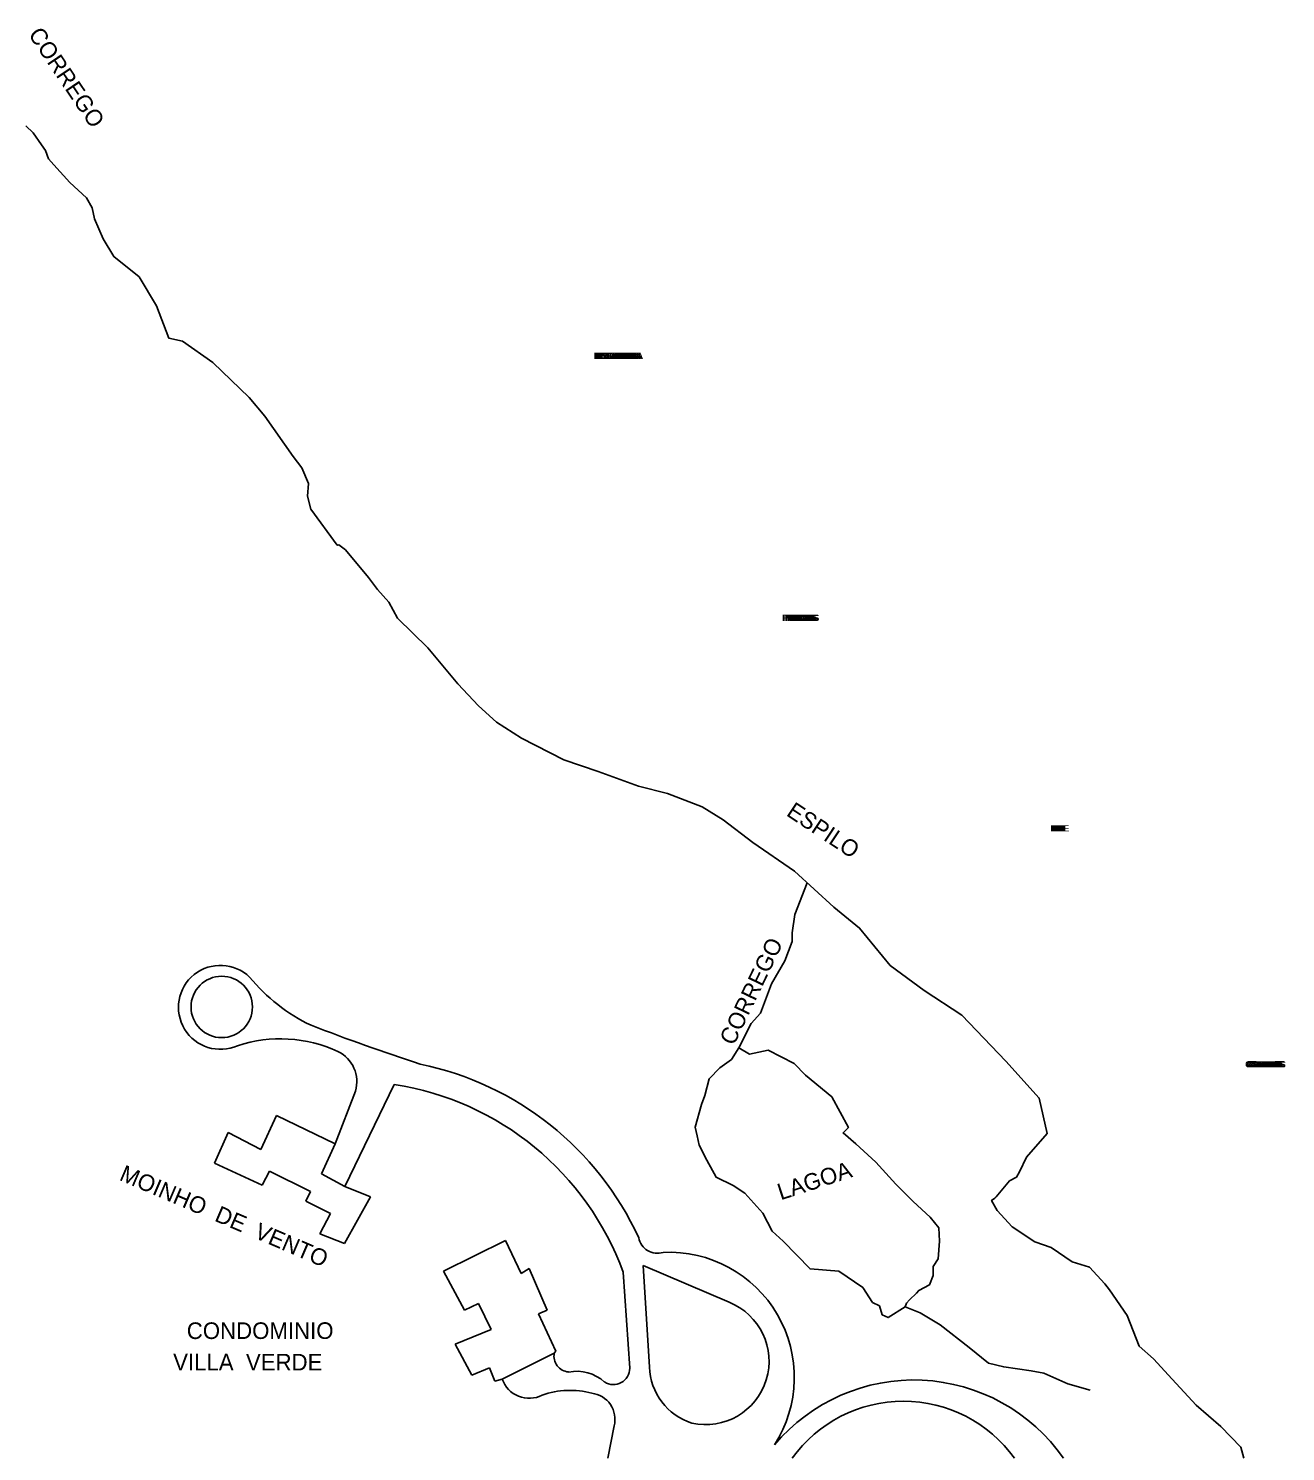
# Model space of a CAD drawing. Extents: x 325709 to 364434, y 7573432 to 7597073.
# Drawn here: x 345101.7 to 345404.6, y 7588503.5 to 7588846.5 of the extents above; entities that cross this region are included whole.
import ezdxf

# ---------------------------------------------------------------- set-up
doc = ezdxf.new("R2010")
doc.units = 0
for name, color, linetype in [('EDIFEXISTENT', 7, 'Continuous'), ('EDIFIDENTIF', 7, 'Continuous'), ('EDIFOBRAEXIS', 7, 'Continuous'), ('LIMITE_BAIRROS_MUNICIPIOS', 7, 'Continuous')]:
    doc.layers.add(name, color=color, linetype=linetype)

msp = doc.modelspace()

# ---------------------------------------------------------------- linework, layer by layer
at = {"layer": 'EDIFEXISTENT'}
for p, q in [((345157.69, 7588576.3), (345161.49, 7588584.55)), ((345161.49, 7588584.55), (345175.64, 7588577.68)), ((345146.54, 7588573.03), (345149.87, 7588580.41)), ((345149.87, 7588580.41), (345157.69, 7588576.3)), ((345175.64, 7588577.68), (345172.36, 7588570.43)), ((345158.02, 7588567.72), (345146.54, 7588573.03)), ((345159.79, 7588571.08), (345158.02, 7588567.72)), ((345169.69, 7588566.19), (345159.79, 7588571.08)), ((345172.36, 7588570.43), (345177.98, 7588567.43)), ((345168.59, 7588563.88), (345169.69, 7588566.19)), ((345184.13, 7588564.95), (345177.89, 7588553.63)), ((345177.98, 7588567.43), (345184.13, 7588564.95)), ((345174.46, 7588560.91), (345168.59, 7588563.88)), ((345171.95, 7588556.01), (345174.46, 7588560.91)), ((345177.89, 7588553.63), (345171.95, 7588556.01)), ((345216.7, 7588554.36), (345201.7, 7588547.03)), ((345220.47, 7588546.44), (345216.7, 7588554.36)), ((345222.41, 7588547.62), (345220.47, 7588546.44)), ((345226.73, 7588537.6), (345222.41, 7588547.62)), ((345201.7, 7588547.03), (345206.77, 7588537.63)), ((345206.77, 7588537.63), (345210.15, 7588539.19)), ((345210.15, 7588539.19), (345213.18, 7588532.97)), ((345224.66, 7588536.75), (345226.73, 7588537.6)), ((345228.81, 7588527.72), (345224.66, 7588536.75)), ((345213.18, 7588532.97), (345204.53, 7588529.38)), ((345204.53, 7588529.38), (345208.57, 7588521.96)), ((345215.88, 7588520.99), (345228.41, 7588527.26)), ((345228.41, 7588527.26), (345228.81, 7588527.72)), ((345208.57, 7588521.96), (345212.84, 7588523.73)), ((345212.84, 7588523.73), (345214.06, 7588520.48)), ((345214.06, 7588520.48), (345215.88, 7588520.99))]:
    msp.add_line(p, q, dxfattribs=at)
at = {"layer": 'EDIFIDENTIF'}
msp.add_circle((345148.29, 7588610.68), 7.4, dxfattribs=at)
at = {"layer": 'EDIFOBRAEXIS'}
for p, q in [((345175.64, 7588577.68), (345180.5, 7588590.38)), ((345189.88, 7588591.97), (345177.98, 7588567.43)), ((345249.82, 7588548.33), (345270.55, 7588539.49)), ((345251.34, 7588523.88), (345249.82, 7588548.33)), ((345246.6, 7588523.61), (345245.05, 7588546.72)), ((345241.34, 7588501.91), (345242.83, 7588509.71))]:
    msp.add_line(p, q, dxfattribs=at)
for points in [[(345101.12, 7588823.09), (345102.83, 7588821.36), (345104.86, 7588818.48), (345105.8, 7588817.09), (345106.52, 7588815.12), (345107.85, 7588813.65), (345111.71, 7588809.39), (345115.72, 7588805.68), (345117.08, 7588803.29), (345117.61, 7588800.68), (345119.75, 7588795.83), (345122.27, 7588791.56), (345128.38, 7588786.68), (345132.57, 7588779.64), (345135.53, 7588771.91), (345138.84, 7588771.15), (345146.13, 7588766.02), (345154.87, 7588757.58), (345158.68, 7588753.05), (345165.49, 7588743.35), (345167.62, 7588740.59), (345169.19, 7588736.83), (345168.94, 7588733.83), (345169.78, 7588730.67), (345176.11, 7588721.96), (345176.51, 7588722.09), (345178.09, 7588720.85), (345183.69, 7588714.21), (345185.83, 7588711.27), (345188.55, 7588708.27), (345190.68, 7588704.39), (345197.97, 7588697.22), (345205.22, 7588688.56), (345210.17, 7588683.23), (345214.48, 7588679.36), (345220.5, 7588675.5), (345230.76, 7588670.24), (345239.02, 7588667.41), (345248.71, 7588663.9), (345255.74, 7588662.09), (345264.03, 7588658.9), (345269.14, 7588655.82), (345276.3, 7588650.35), (345286.29, 7588643.43), (345295.8, 7588634.75), (345301.98, 7588629.7), (345309.34, 7588620.68), (345317.55, 7588614.67), (345326.63, 7588608.73), (345337.22, 7588597.63), (345345.28, 7588588.72), (345347.16, 7588580.21), (345342.25, 7588574.46), (345340.51, 7588570.97), (345339.82, 7588569.68), (345338.13, 7588568.74), (345334.9, 7588564.92), (345334.55, 7588564.63), (345333.82, 7588564.06), (345335.16, 7588561.6), (345338.79, 7588557.69), (345344.19, 7588554.08), (345348.13, 7588552.72), (345353.22, 7588549.23), (345357.44, 7588547.98), (345361.09, 7588543.95), (345362.21, 7588542.47), (345366.46, 7588536.29), (345369.36, 7588528.89), (345372.85, 7588525.85), (345377.36, 7588521), (345383.11, 7588514.72), (345389.05, 7588509.54), (345393.89, 7588504.56), (345394.61, 7588501.91)], [(345289.37, 7588640.61), (345286.39, 7588632.99), (345285.76, 7588628.53), (345285.77, 7588626.47), (345284, 7588621.78), (345280.77, 7588616.26), (345278.09, 7588609.17), (345275.9, 7588606.69), (345272.9, 7588600.82), (345275.44, 7588599.31), (345279.95, 7588600.26), (345286.24, 7588597.06), (345288.98, 7588594.21), (345295.33, 7588589.01), (345299.32, 7588581.66), (345298, 7588580.34), (345301.07, 7588577.7), (345305.92, 7588573.26), (345310.72, 7588567.98), (345314.94, 7588563.78), (345318.97, 7588560.01), (345321.12, 7588557.48), (345321.28, 7588554.23), (345320.92, 7588550.01), (345319.71, 7588548.13), (345319.72, 7588545.92), (345318.87, 7588543.72), (345316.25, 7588542.35), (345315.73, 7588541.71), (345314.06, 7588540.05), (345313.28, 7588539.27), (345312.99, 7588538.43), (345316.6, 7588536.99), (345321.43, 7588534.08), (345328.44, 7588528.56), (345333.06, 7588524.85), (345336.74, 7588523.9), (345343.36, 7588522.97), (345346.37, 7588522.39), (345352.19, 7588519.85), (345357.55, 7588518.34)], [(345272.9, 7588600.82), (345271.1, 7588597.99), (345268.33, 7588596.04), (345265.76, 7588593.35), (345264.74, 7588589.31), (345263.89, 7588587.19), (345262.36, 7588581.72), (345262.88, 7588579.62), (345263.35, 7588577.37), (345265.16, 7588573.76), (345267.4, 7588569.63), (345271.53, 7588567.67), (345274.33, 7588565.82), (345278.66, 7588560.99), (345280.9, 7588556.63), (345283.58, 7588554.21), (345290.05, 7588547.53), (345297, 7588547.02), (345302.74, 7588543.03), (345305.14, 7588539.44), (345306.79, 7588538.63), (345307.46, 7588536.5), (345308.92, 7588535.82), (345312.99, 7588538.43)]]:
    msp.add_lwpolyline(points, dxfattribs=at)
for centre, radius, start, end in [((345147.99, 7588610.59), 10.12, 46.0327, 294.0123), ((345188.23, 7588644.97), 42.86, 219.2032, 244.5668), ((345392.55, 7589189.34), 624.18, 249.09402, 251.65702), ((345162.44, 7588570.35), 32.66, 64.9176, 108.4321), ((345172.84, 7588592.71), 8, 343.1003, 64.5401), ((345181.19, 7588524.06), 74.34, 24.6302, 78.4116), ((345179.28, 7588522.79), 69.99, 19.996, 81.2892), ((345253.27, 7588555.91), 4.59, 190.9406, 287.5251), ((345256.07, 7588521.39), 30.18, 327.3984, 92.7059), ((345264.9, 7588525.29), 15.28, 257.4947, 68.3136), ((345232.24, 7588526.57), 3.89, 169.7853, 264.5407), ((345242.69, 7588523.56), 3.91, 236.7813, 0.8555), ((345266.05, 7588524.4), 14.72, 182.0125, 252.3537), ((345222.34, 7588523.16), 6.81, 198.552, 297.6243), ((345233.8, 7588512.83), 10.05, 47.8492, 101.0884), ((345315.07, 7588476.9), 43.87, 34.7617, 139.9391), ((345232.18, 7588498.21), 20.06, 74.684, 109.4511), ((345236.77, 7588511.32), 6.28, 345.1871, 83.5026), ((345312.56, 7588482.73), 32.94, 35.6043, 144.3957)]:
    msp.add_arc(centre, radius, start, end, dxfattribs=at)

# ---------------------------------------------------------------- texts
at = {"layer": 'EDIFIDENTIF'}
for s, rotation, p in [('CORREGO', 304.0003, (345101.55, 7588845.09)), ('ESPILO', 326.4661, (345284.12, 7588656.96)), ('CORREGO', 64.3439, (345271.68, 7588601.18)), ('MOINHO  DE  VENTO', 336.7982, (345123.38, 7588569.04)), ('LAGOA', 17.9928, (345282.98, 7588564.06)), ('CONDOMINIO', 0.0322, (345139.87, 7588530.65)), ('VILLA  VERDE', 359.9762, (345136.58, 7588523.08))]:
    msp.add_text(s, height=4, rotation=rotation, dxfattribs=at).set_placement(p)
at = {"layer": 'LIMITE_BAIRROS_MUNICIPIOS'}
for s, p in [('ESTANCIA', (345237.95, 7588766.89)), ('ESTANCIA', (345238.15, 7588766.89)), ('ESTANCIA', (345238.35, 7588766.89)), ('ESTANCIA', (345238.55, 7588766.89)), ('ESTANCIA', (345238.75, 7588766.89)), ('ESTANCIA', (345238.95, 7588766.89)), ('ESTANCIA', (345239.15, 7588766.89)), ('ESTANCIA', (345239.35, 7588766.89)), ('ESTANCIA', (345239.55, 7588766.89)), ('ESTANCIA', (345239.75, 7588766.89)), ('POCOS', (345283.27, 7588703.73)), ('POCOS', (345283.47, 7588703.73)), ('POCOS', (345283.67, 7588703.73)), ('POCOS', (345283.87, 7588703.73)), ('POCOS', (345284.07, 7588703.73)), ('POCOS', (345284.27, 7588703.73)), ('POCOS', (345284.47, 7588703.73)), ('POCOS', (345284.67, 7588703.73)), ('POCOS', (345284.87, 7588703.73)), ('POCOS', (345285.07, 7588703.73)), ('DE', (345347.94, 7588652.98)), ('DE', (345348.14, 7588652.98)), ('DE', (345348.34, 7588652.98)), ('DE', (345348.54, 7588652.98)), ('DE', (345348.74, 7588652.98)), ('DE', (345348.94, 7588652.98)), ('DE', (345349.14, 7588652.98)), ('DE', (345349.34, 7588652.98)), ('DE', (345349.54, 7588652.98)), ('DE', (345349.74, 7588652.98)), ('CALDAS', (345394.9, 7588596.11)), ('CALDAS', (345395.1, 7588596.11)), ('CALDAS', (345395.3, 7588596.11)), ('CALDAS', (345395.5, 7588596.11)), ('CALDAS', (345395.7, 7588596.11)), ('CALDAS', (345395.9, 7588596.11)), ('CALDAS', (345396.1, 7588596.11)), ('CALDAS', (345396.3, 7588596.11)), ('CALDAS', (345396.5, 7588596.11)), ('CALDAS', (345396.7, 7588596.11))]:
    msp.add_text(s, height=1.5, dxfattribs=at).set_placement(p)

doc.saveas('drawing.dxf')
